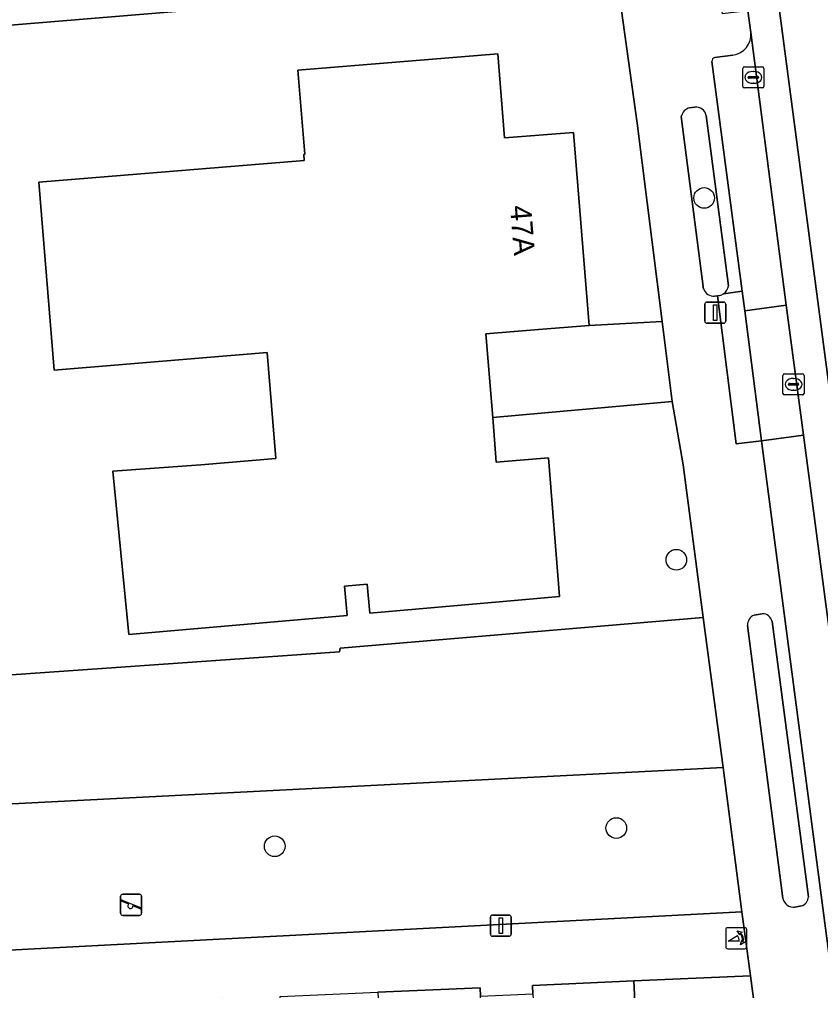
# Model space of a CAD drawing. Extents: x 160554 to 161248, y 385329 to 386506.
# Drawn here: x 161103.88 to 161141.82, y 385475.1 to 385521.08 of the extents above; entities that cross this region are included whole.
import ezdxf

# ---------------------------------------------------------------- set-up
doc = ezdxf.new("R2010")
doc.units = 0
for name, color, linetype in [('IMGEO_Boom', 7, 'Continuous'), ('IMGEO_Erf', 7, 'Continuous'), ('IMGEO_Groenvoorziening', 7, 'Continuous'), ('IMGEO_Kolk', 7, 'Continuous'), ('IMGEO_Lichtmast', 7, 'Continuous'), ('IMGEO_Pand', 7, 'Continuous'), ('IMGEO_Pand_nummerreeks', 7, 'Continuous'), ('IMGEO_Parkeervlak_open', 7, 'Continuous'), ('IMGEO_Poller', 7, 'Continuous'), ('IMGEO_Rijbaan_lokaal_gesloten', 7, 'Continuous'), ('IMGEO_Rijbaan_lokaal_open', 7, 'Continuous'), ('IMGEO_Speelvoorziening', 7, 'Continuous'), ('IMGEO_Voetpad_open', 7, 'Continuous')]:
    doc.layers.add(name, color=color, linetype=linetype)

msp = doc.modelspace()

# ---------------------------------------------------------------- linework, layer by layer
at = {"layer": 'IMGEO_Boom'}
for centre in [(161136.305, 385512.629), (161134.988, 385495.497), (161132.146, 385482.792), (161115.969, 385481.932)]:
    msp.add_circle(centre, 0.489, dxfattribs=at)
at = {"layer": 'IMGEO_Erf'}
for points in [[(161133.129, 385516.169), (161132.125, 385523.449), (161118.748, 385522.087), (161098.852, 385520.428), (161099.614, 385512.321), (161096.798, 385512.189), (161096.834, 385511.893), (161098.073, 385511.953), (161098.284, 385508.638), (161098.064, 385508.211)], [(161102.588, 385489.988), (161119.033, 385491.139), (161119.071, 385491.304), (161136.266, 385492.761), (161135.316, 385500), (161134.793, 385502.989), (161128.767, 385502.45), (161126.292, 385502.229), (161126.456, 385500.112), (161128.932, 385500.33), (161129.45, 385493.76), (161126.965, 385493.541), (161120.475, 385492.968), (161120.353, 385494.343), (161119.274, 385494.248), (161119.396, 385492.865), (161109.065, 385491.954), (161108.301, 385499.694), (161112.466, 385500), (161116.025, 385500.29), (161115.616, 385505.305), (161105.527, 385504.483), (161104.802, 385513.376), (161117.369, 385514.4), (161117.345, 385514.694), (161117.389, 385514.698), (161117.064, 385518.684), (161126.533, 385519.456), (161126.858, 385515.469), (161130.117, 385515.735), (161130.862, 385506.593), (161134.314, 385506.782), (161133.129, 385516.169)], [(161138.499, 385475.796), (161132.97, 385475.555), (161133.109, 385472.9)], [(161140.942, 385457.289), (161138.499, 385475.796)]]:
    msp.add_lwpolyline(points, dxfattribs=at)
at = {"layer": 'IMGEO_Groenvoorziening'}
for points in [[(161135.858, 385516.927), (161135.615, 385516.9)], [(161135.224, 385516.485), (161136.282, 385508.308)], [(161137.459, 385508.463), (161136.399, 385516.537)], [(161136.794, 385507.979), (161136.937, 385507.995), (161137.039, 385508.006)], [(161139.058, 385492.938), (161138.668, 385492.88)], [(161141.246, 385479.544), (161139.524, 385492.571)], [(161138.355, 385492.387), (161139.89, 385480.569), (161140.036, 385479.464)], [(161140.603, 385479.046), (161140.913, 385479.104)]]:
    msp.add_lwpolyline(points, dxfattribs=at)
for points in [[(161137.199, 385485.658), (161136.266, 385492.761), (161119.071, 385491.304), (161119.033, 385491.139), (161102.588, 385489.988), (161101.718, 385489.917), (161080.166, 385488.17), (161077.103, 385483.331), (161077.279, 385482.601)], [(161138.095, 385478.829), (161137.199, 385485.658), (161077.279, 385482.601), (161078.932, 385475.726)]]:
    msp.add_lwpolyline(points, close=True, dxfattribs=at)
for centre, radius, start, end in [((161135.756, 385516.375), 0.543, 105.062, 168.3491), ((161135.921, 385516.444), 0.487, 10.9872, 97.4381), ((161136.764, 385508.494), 0.516, 201.1683, 273.3838), ((161136.873, 385508.58), 0.597, 306.0811, 348.7337), ((161136.883, 385508.56), 0.575, 285.7022, 306.438), ((161139.081, 385492.487), 0.451, 10.6806, 92.8747), ((161138.886, 385492.396), 0.531, 114.2194, 180.9586), ((161140.541, 385479.555), 0.513, 190.2545, 276.9492), ((161140.762, 385479.564), 0.484, 288.1384, 357.6234)]:
    msp.add_arc(centre, radius, start, end, dxfattribs=at)
at = {"layer": 'IMGEO_Kolk'}
for p, q in [((161138.134, 385517.912), (161138.134, 385518.764)), ((161138.209, 385518.838), (161139.061, 385518.838)), ((161139.135, 385518.764), (161139.135, 385517.912)), ((161138.393, 385518.332), (161138.393, 385518.344)), ((161138.831, 385518.295), (161138.433, 385518.295)), ((161138.436, 385518.381), (161138.834, 385518.381)), ((161138.622, 385518.618), (161138.647, 385518.618)), ((161138.877, 385518.344), (161138.877, 385518.332)), ((161139.061, 385517.838), (161138.209, 385517.838)), ((161138.645, 385518.058), (161138.62, 385518.058)), ((161140.037, 385503.377), (161140.037, 385504.229)), ((161140.112, 385504.303), (161140.964, 385504.303)), ((161140.525, 385504.083), (161140.55, 385504.083)), ((161141.038, 385504.229), (161141.038, 385503.377)), ((161140.296, 385503.797), (161140.296, 385503.809)), ((161140.734, 385503.76), (161140.336, 385503.76)), ((161140.339, 385503.846), (161140.737, 385503.846)), ((161140.548, 385503.523), (161140.523, 385503.523)), ((161140.78, 385503.809), (161140.78, 385503.797)), ((161140.964, 385503.303), (161140.112, 385503.303))]:
    msp.add_line(p, q, dxfattribs=at)
for points in [[(161138.134, 385517.912), (161138.134, 385518.764)], [(161138.209, 385518.838), (161139.061, 385518.838)], [(161139.135, 385518.764), (161139.135, 385517.912)], [(161139.061, 385517.838), (161138.209, 385517.838)], [(161140.037, 385503.377), (161140.037, 385504.229)], [(161140.112, 385504.303), (161140.964, 385504.303)], [(161141.038, 385504.229), (161141.038, 385503.377)], [(161140.964, 385503.303), (161140.112, 385503.303)]]:
    msp.add_lwpolyline(points, dxfattribs=at)
for centre, radius, start, end in [((161138.211, 385518.762), 0.0765, 91.552, 178.448), ((161138.211, 385518.762), 0.0765, 91.552, 178.448), ((161139.059, 385518.762), 0.0765, 1.552, 88.448), ((161139.059, 385518.762), 0.0765, 1.552, 88.448), ((161138.433, 385518.341), 0.0403, 85.8775, 175.7526), ((161138.43, 385518.331), 0.0366, 178.938, 274.7102), ((161138.834, 385518.338), 0.043, 264.8664, 352.4533), ((161138.838, 385518.343), 0.0386, 1.7309, 96.639), ((161138.211, 385517.914), 0.0765, 181.552, 268.448), ((161138.211, 385517.914), 0.0765, 181.552, 268.448), ((161139.059, 385517.914), 0.0765, 271.552, 358.448), ((161139.059, 385517.914), 0.0765, 271.552, 358.448), ((161140.114, 385504.227), 0.0765, 91.552, 178.448), ((161140.114, 385504.227), 0.0765, 91.552, 178.448), ((161140.962, 385504.227), 0.0765, 1.552, 88.448), ((161140.962, 385504.227), 0.0765, 1.552, 88.448), ((161140.336, 385503.806), 0.0403, 85.8775, 175.7526), ((161140.333, 385503.796), 0.0366, 178.938, 274.7102), ((161140.737, 385503.803), 0.043, 264.8664, 352.4533), ((161140.741, 385503.808), 0.0386, 1.7309, 96.639), ((161140.114, 385503.379), 0.0765, 181.552, 268.448), ((161140.114, 385503.379), 0.0765, 181.552, 268.448), ((161140.962, 385503.379), 0.0765, 271.552, 358.448), ((161140.962, 385503.379), 0.0765, 271.552, 358.448)]:
    msp.add_arc(centre, radius, start, end, dxfattribs=at)
for centre, major_axis, ratio, start_param, end_param in [((161138.621, 385518.338), (-0.387, 0.002), 0.722429, 4.712389, 7.853982), ((161138.646, 385518.338), (-0.39, 0.002), 0.717154, 1.570796, 4.712389), ((161140.524, 385503.803), (-0.387, 0.002), 0.722429, 4.712389, 7.853982), ((161140.549, 385503.803), (-0.39, 0.002), 0.717154, 1.570796, 4.712389)]:
    msp.add_ellipse(centre, major_axis=major_axis, ratio=ratio, start_param=start_param, end_param=end_param, dxfattribs=at)
at = {"layer": 'IMGEO_Lichtmast'}
for p, q in [((161136.435, 385507.698), (161137.225, 385507.698)), ((161137.225, 385507.698), (161136.435, 385507.698)), ((161136.335, 385506.798), (161136.335, 385507.598)), ((161136.335, 385507.598), (161136.335, 385506.798)), ((161137.325, 385507.598), (161137.325, 385506.798)), ((161137.325, 385506.798), (161137.325, 385507.598)), ((161137.225, 385506.698), (161136.435, 385506.698)), ((161136.435, 385506.698), (161137.225, 385506.698)), ((161126.182, 385477.772), (161126.182, 385478.572)), ((161126.182, 385478.572), (161126.182, 385477.772)), ((161126.282, 385478.672), (161127.072, 385478.672)), ((161127.072, 385478.672), (161126.282, 385478.672)), ((161127.172, 385478.572), (161127.172, 385477.772)), ((161127.172, 385477.772), (161127.172, 385478.572)), ((161127.072, 385477.672), (161126.282, 385477.672)), ((161126.282, 385477.672), (161127.072, 385477.672))]:
    msp.add_line(p, q, dxfattribs=at)
for points in [[(161136.755, 385507.573), (161136.905, 385507.573), (161136.905, 385506.823), (161136.755, 385506.823), (161136.755, 385507.573)], [(161126.602, 385478.547), (161126.752, 385478.547), (161126.752, 385477.797), (161126.602, 385477.797), (161126.602, 385478.547)]]:
    msp.add_lwpolyline(points, dxfattribs=at)
for centre, start, end in [((161136.435, 385507.598), 90, 180), ((161136.435, 385507.598), 90, 180), ((161137.225, 385507.598), 0, 90), ((161137.225, 385507.598), 360, 90), ((161136.435, 385506.798), 180, 270), ((161136.435, 385506.798), 180, 270), ((161137.225, 385506.798), 270, 0), ((161137.225, 385506.798), 270, 0), ((161126.282, 385478.572), 90, 180), ((161126.282, 385478.572), 90, 180), ((161127.072, 385478.572), 0, 90), ((161127.072, 385478.572), 360, 90), ((161126.282, 385477.772), 180, 270), ((161126.282, 385477.772), 180, 270), ((161127.072, 385477.772), 270, 0), ((161127.072, 385477.772), 270, 0)]:
    msp.add_arc(centre, 0.1, start, end, dxfattribs=at)
at = {"layer": 'IMGEO_Pand'}
for points in [[(161130.862, 385506.593), (161130.117, 385515.735), (161126.858, 385515.469), (161126.533, 385519.456), (161117.064, 385518.684), (161117.389, 385514.698), (161117.345, 385514.694), (161117.369, 385514.4), (161104.802, 385513.376), (161105.527, 385504.483), (161115.616, 385505.305), (161116.025, 385500.29), (161112.466, 385500), (161108.301, 385499.694), (161109.065, 385491.954), (161119.396, 385492.865), (161119.274, 385494.248), (161120.353, 385494.343), (161120.475, 385492.968), (161126.965, 385493.541), (161129.45, 385493.76), (161128.932, 385500.33), (161126.456, 385500.112), (161126.292, 385502.229), (161125.968, 385506.194), (161128.46, 385506.397)], [(161132.97, 385475.555), (161128.172, 385475.343), (161128.193, 385474.937), (161128.311, 385472.688), (161133.109, 385472.9)], [(161125.713, 385474.836), (161125.695, 385475.233), (161120.845, 385475.019), (161120.988, 385472.364), (161125.813, 385472.577)]]:
    msp.add_lwpolyline(points, close=True, dxfattribs=at)
at = {"layer": 'IMGEO_Parkeervlak_open'}
for points in [[(161136.671, 385519.089), (161138.106, 385508.213), (161138.228, 385507.289), (161140.193, 385507.547), (161138.515, 385520.471)], [(161137.663, 385519.395), (161136.807, 385519.282)]]:
    msp.add_lwpolyline(points, dxfattribs=at)
for centre, radius, start, end in [((161137.548, 385520.362), 0.973, 276.8032, 6.451), ((161136.858, 385519.102), 0.187, 105.7994, 183.8587)]:
    msp.add_arc(centre, radius, start, end, dxfattribs=at)
at = {"layer": 'IMGEO_Poller'}
for p, q in [((161137.328, 385477.979), (161137.328, 385477.172)), ((161137.328, 385477.979), (161137.328, 385477.172)), ((161138.23, 385478.074), (161137.422, 385478.074)), ((161138.23, 385478.074), (161137.422, 385478.074)), ((161138.324, 385477.172), (161138.324, 385477.979)), ((161138.324, 385477.172), (161138.324, 385477.979)), ((161137.422, 385477.077), (161138.23, 385477.077)), ((161137.422, 385477.077), (161138.23, 385477.077))]:
    msp.add_line(p, q, dxfattribs=at)
for points in [[(161138.007, 385477.803), (161137.995, 385477.73), (161137.87, 385477.935)], [(161137.87, 385477.935), (161138.101, 385477.869), (161138.03, 385477.837)], [(161137.963, 385477.43), (161137.45, 385477.43), (161137.88, 385477.705)], [(161138.023, 385477.258), (161138.089, 385477.489), (161138.119, 385477.421)], [(161138.155, 385477.394), (161138.227, 385477.383), (161138.023, 385477.258)]]:
    msp.add_lwpolyline(points, dxfattribs=at)
for centre, radius, start, end in [((161137.422, 385477.979), 0.0946, 90, 180), ((161137.422, 385477.979), 0.0946, 90, 180), ((161137.649, 385477.49), 0.476, 351.7527, 41.1691), ((161137.649, 385477.49), 0.516, 349.3569, 42.2912), ((161138.23, 385477.979), 0.0946, 0, 90), ((161138.23, 385477.979), 0.0946, 0, 90), ((161137.635, 385477.48), 0.332, 351.3247, 42.4854), ((161137.422, 385477.172), 0.0946, 180, 270), ((161137.422, 385477.172), 0.0946, 180, 270), ((161138.23, 385477.172), 0.0946, 270, 0), ((161138.23, 385477.172), 0.0946, 270, 0)]:
    msp.add_arc(centre, radius, start, end, dxfattribs=at)
at = {"layer": 'IMGEO_Rijbaan_lokaal_gesloten'}
msp.add_lwpolyline([(161129.001, 385603.744), (161126.296, 385624.071), (161124.809, 385623.89), (161124.823, 385623.758), (161127.335, 385604.916), (161131.436, 385573.892), (161131.444, 385573.829), (161131.983, 385569.741), (161132.394, 385566.679), (161136.719, 385534.065), (161137.405, 385528.949), (161137.609, 385527.41), (161138.381, 385521.493), (161138.515, 385520.471), (161140.193, 385507.547), (161141.009, 385501.397), (161143.236, 385484.558), (161144.696, 385484.751), (161142.364, 385502.586), (161138.335, 385533.123)], close=True, dxfattribs=at)
for points in [[(161141.009, 385501.397), (161139.019, 385501.128), (161144.514, 385459.302)], [(161146.64, 385458.491), (161145.077, 385470.113), (161144.974, 385471.165), (161143.377, 385483.491), (161143.236, 385484.558), (161141.009, 385501.397)]]:
    msp.add_lwpolyline(points, dxfattribs=at)
at = {"layer": 'IMGEO_Rijbaan_lokaal_open'}
for points in [[(161140.522, 385535.764), (161128.787, 385624.365), (161126.296, 385624.071), (161129.001, 385603.744), (161138.335, 385533.123), (161142.364, 385502.586), (161144.696, 385484.751), (161147.193, 385485.072)], [(161140.193, 385507.547), (161138.228, 385507.289), (161139.019, 385501.128), (161141.009, 385501.397)]]:
    msp.add_lwpolyline(points, close=True, dxfattribs=at)
at = {"layer": 'IMGEO_Speelvoorziening'}
for p, q in [((161108.774, 385479.661), (161109.564, 385479.661)), ((161109.564, 385479.661), (161108.774, 385479.661)), ((161108.674, 385478.761), (161108.674, 385479.561)), ((161108.674, 385479.561), (161108.674, 385478.761)), ((161109.057, 385479.189), (161108.718, 385479.326)), ((161108.743, 385479.386), (161109.619, 385479.033)), ((161109.664, 385479.561), (161109.664, 385478.761)), ((161109.664, 385478.761), (161109.664, 385479.561)), ((161109.595, 385478.973), (161109.255, 385479.11)), ((161109.564, 385478.661), (161108.774, 385478.661)), ((161108.774, 385478.661), (161109.564, 385478.661))]:
    msp.add_line(p, q, dxfattribs=at)
for centre, radius, start, end in [((161108.774, 385479.561), 0.1, 90, 180), ((161108.774, 385479.561), 0.1, 90, 180), ((161109.564, 385479.561), 0.1, 0, 90), ((161109.564, 385479.561), 0.1, 360, 90), ((161108.731, 385479.356), 0.0327, 68.078, 248.078), ((161109.136, 385479.099), 0.12, 130.9928, 5.1632), ((161108.774, 385478.761), 0.1, 180, 270), ((161108.774, 385478.761), 0.1, 180, 270), ((161109.564, 385478.761), 0.1, 270, 0), ((161109.564, 385478.761), 0.1, 270, 0), ((161109.607, 385479.003), 0.0327, 248.078, 68.078)]:
    msp.add_arc(centre, radius, start, end, dxfattribs=at)
at = {"layer": 'IMGEO_Voetpad_open'}
for points in [[(161136.341, 385529.83), (161135.137, 385529.71), (161135.418, 385526.832), (161130.558, 385526.389), (161130.319, 385529.237), (161128.796, 385529.094), (161129.051, 385526.24), (161132.125, 385523.449), (161133.129, 385516.169), (161134.314, 385506.782), (161134.793, 385502.989), (161135.316, 385500), (161136.266, 385492.761), (161137.199, 385485.658), (161138.095, 385478.829), (161138.499, 385475.796), (161140.942, 385457.289)], [(161138.515, 385520.471), (161138.381, 385521.493), (161137.18, 385521.344), (161136.42, 385527.265), (161137.609, 385527.41), (161137.405, 385528.949)], [(161074.274, 385518.185), (161077.669, 385518.505), (161098.852, 385520.428), (161118.748, 385522.087), (161132.125, 385523.449), (161129.051, 385526.24), (161123.108, 385525.73), (161121.73, 385525.612), (161102.391, 385523.95)], [(161136.807, 385519.282), (161137.663, 385519.395)], [(161137.225, 385508.097), (161138.106, 385508.213), (161136.671, 385519.089)], [(161135.615, 385516.9), (161135.858, 385516.927)], [(161136.282, 385508.308), (161135.224, 385516.485)], [(161136.399, 385516.537), (161137.459, 385508.463)], [(161138.228, 385507.289), (161138.106, 385508.213), (161137.225, 385508.097)], [(161144.514, 385459.302), (161139.019, 385501.128), (161137.826, 385500.985), (161136.937, 385507.995), (161136.794, 385507.979)], [(161137.039, 385508.006), (161136.937, 385507.995), (161137.826, 385500.985), (161139.019, 385501.128), (161138.228, 385507.289)], [(161138.668, 385492.88), (161139.058, 385492.938)], [(161139.524, 385492.571), (161141.246, 385479.544)], [(161140.036, 385479.464), (161139.89, 385480.569), (161138.355, 385492.387)], [(161069.71, 385472.482), (161076.464, 385472.863), (161079.665, 385472.955), (161100.981, 385474.144), (161102.66, 385474.238), (161107.462, 385474.476), (161108.778, 385474.498), (161113.496, 385474.74), (161113.516, 385474.343), (161116.241, 385474.444), (161116.23, 385474.815), (161120.845, 385475.019), (161125.695, 385475.233), (161125.713, 385474.836), (161128.193, 385474.937), (161128.172, 385475.343), (161132.97, 385475.555), (161138.499, 385475.796), (161138.095, 385478.829), (161078.932, 385475.726), (161075.831, 385475.76), (161073.558, 385475.649), (161059.018, 385474.939)], [(161140.913, 385479.104), (161140.603, 385479.046)]]:
    msp.add_lwpolyline(points, dxfattribs=at)
msp.add_lwpolyline([(161128.767, 385502.45), (161134.793, 385502.989), (161134.314, 385506.782), (161130.862, 385506.593), (161128.46, 385506.397), (161125.968, 385506.194), (161126.292, 385502.229)], close=True, dxfattribs=at)
for centre, radius, start, end in [((161137.548, 385520.362), 0.973, 276.8032, 6.451), ((161136.858, 385519.102), 0.187, 105.7994, 183.8587), ((161135.756, 385516.375), 0.543, 105.062, 168.3491), ((161135.921, 385516.444), 0.487, 10.9872, 97.4381), ((161136.764, 385508.494), 0.516, 201.1683, 273.3838), ((161136.873, 385508.58), 0.597, 306.0811, 348.7337), ((161136.883, 385508.56), 0.575, 285.7022, 306.438), ((161139.081, 385492.487), 0.451, 10.6806, 92.8747), ((161138.886, 385492.396), 0.531, 114.2194, 180.9586), ((161140.541, 385479.555), 0.513, 190.2545, 276.9492), ((161140.762, 385479.564), 0.484, 288.1384, 357.6234)]:
    msp.add_arc(centre, radius, start, end, dxfattribs=at)

# ---------------------------------------------------------------- texts
at = {"layer": 'IMGEO_Pand_nummerreeks'}
msp.add_text('47A', height=1, rotation=274.6589, dxfattribs=at).set_placement((161127.11, 385512.249))

doc.saveas('drawing.dxf')
